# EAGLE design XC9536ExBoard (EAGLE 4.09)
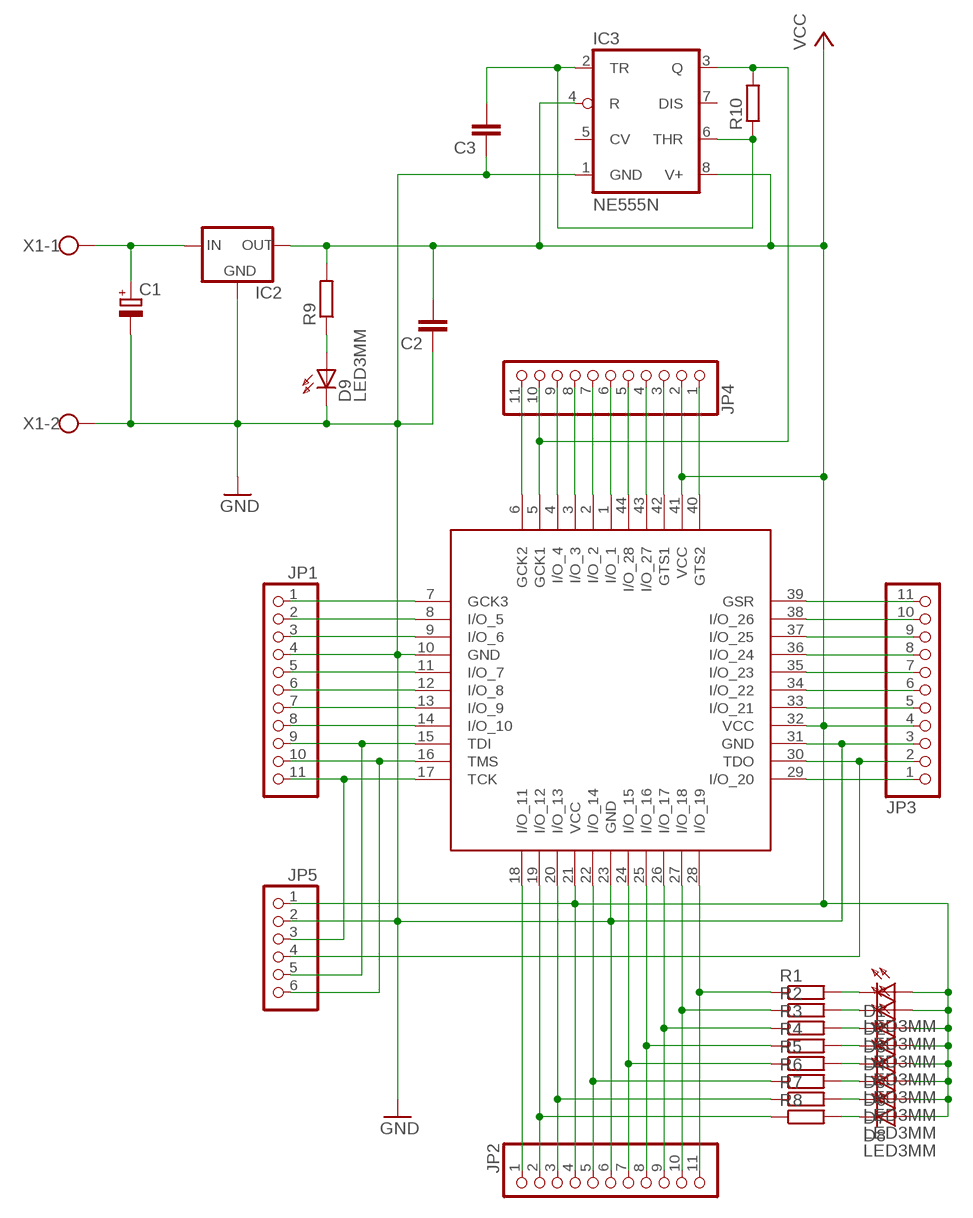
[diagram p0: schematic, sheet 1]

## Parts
C1  CPOL-EUE2.5-6  [E2,5-6]
C2  C-EU050-025X075  [C050-025X075]
C3  C-EU050-025X075  [C050-025X075]
D1  LED3MM  [LED3MM]
D2  LED3MM  [LED3MM]
D3  LED3MM  [LED3MM]
D4  LED3MM  [LED3MM]
D5  LED3MM  [LED3MM]
D6  LED3MM  [LED3MM]
D7  LED3MM  [LED3MM]
D8  LED3MM  [LED3MM]
D9  LED3MM  [LED3MM]
IC1  XC9536PLCC44S  [S44]
IC2  78XXL  [78XXL]
IC3  NE555N  [DIL08]
JP1  PINHD-1X11  [1X11]
JP2  PINHD-1X11  [1X11]
JP3  PINHD-1X11  [1X11]
JP4  PINHD-1X11  [1X11]
JP5  PINHD-1X6  [1X06]
R1  R-EU_0207/10  [0207/10]
R2  R-EU_0207/10  [0207/10]
R3  R-EU_0207/10  [0207/10]
R4  R-EU_0207/10  [0207/10]
R5  R-EU_0207/10  [0207/10]
R6  R-EU_0207/10  [0207/10]
R7  R-EU_0207/10  [0207/10]
R8  R-EU_0207/10  [0207/10]
R9  R-EU_0207/10  [0207/10]
R10  R-EU_0207/10  [0207/10]
X1  W237-02P  [W237-132]

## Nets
GND: C1.- C2.1 C3.1 D9.K(C) IC1.10(GND) IC1.23(GND) IC1.31(GND) IC2.GND IC3.1(GND) JP1.4 JP2.6 JP3.3 JP5.2 X1.2
N$1: IC1.18(I/O_11) JP2.1
N$2: IC1.19(I/O_12) JP2.2 R8.1
N$3: IC1.7(GCK3) JP1.1
N$4: IC1.8(I/O_5) JP1.2
N$5: IC1.9(I/O_6) JP1.3
N$6: IC1.11(I/O_7) JP1.5
N$7: IC1.12(I/O_8) JP1.6
N$8: IC1.13(I/O_9) JP1.7
N$9: IC1.14(I/O_10) JP1.8
N$10: IC1.15(TDI) JP1.9 JP5.5
N$11: IC1.16(TMS) JP1.10 JP5.6
N$12: IC1.17(TCK) JP1.11 JP5.3
N$13: IC1.20(I/O_13) JP2.3 R7.1
N$14: D1.K(C) R1.2
N$15: IC1.22(I/O_14) JP2.5 R6.1
N$16: IC1.24(I/O_15) JP2.7 R5.1
N$17: IC1.25(I/O_16) JP2.8 R4.1
N$18: IC1.26(I/O_17) JP2.9 R3.1
N$19: IC1.27(I/O_18) JP2.10 R2.1
N$20: IC1.28(I/O_19) JP2.11 R1.1
N$21: IC1.29(I/O_20) JP3.1
N$22: IC1.30(TDO) JP3.2 JP5.4
N$23: D2.K(C) R2.2
N$24: IC1.33(I/O_21) JP3.5
N$25: IC1.34(I/O_22) JP3.6
N$26: IC1.35(I/O_23) JP3.7
N$27: IC1.36(I/O_24) JP3.8
N$28: IC1.37(I/O_25) JP3.9
N$29: IC1.38(I/O_26) JP3.10
N$30: IC1.39(GSR) JP3.11
N$31: IC1.40(GTS2) JP4.1
N$32: D3.K(C) R3.2
N$33: IC1.42(GTS1) JP4.3
N$34: IC1.43(I/O_27) JP4.4
N$35: IC1.44(I/O_28) JP4.5
N$36: IC1.1(I/O_1) JP4.6
N$37: IC1.2(I/O_2) JP4.7
N$38: IC1.3(I/O_3) JP4.8
N$39: IC1.4(I/O_4) JP4.9
N$40: IC1.5(GCK1) IC3.3(Q) JP4.10 R10.2
N$41: IC1.6(GCK2) JP4.11
N$42: D4.K(C) R4.2
N$43: D5.K(C) R5.2
N$44: D6.K(C) R6.2
N$45: D7.K(C) R7.2
N$46: D8.K(C) R8.2
N$47: C1.+ IC2.IN X1.1
N$48: D9.A R9.1
N$50: C3.2 IC3.2(TR) IC3.6(THR) R10.1
VCC: C2.2 D1.A D2.A D3.A D4.A D5.A D6.A D7.A D8.A IC1.21(VCC) IC1.32(VCC) IC1.41(VCC) IC2.OUT IC3.4(R) IC3.8(V+) JP2.4 JP3.4 JP4.2 JP5.1 R9.2
Unconnected: IC3.5(CV) IC3.7(DIS)

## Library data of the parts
C1 = rcl:CPOL-EU: POLARIZED CAPACITOR, European symbol
C2 C3 = rcl:C-EU: CAPACITOR, European symbol
D1-D9 = led:LED3MM: LED
IC1 = xilinx:XC9536: Xilinx CPLD Cells 36 Gates 800
IC2 = v-reg:78XXL: VOLTAGE REGULATOR
IC3 = linear:*555: TIMER
JP1-JP4 = pinhead:PINHD-1X11: PIN HEADER
JP5 = pinhead:PINHD-1X6: PIN HEADER
R1-R10 = rcl:R-EU_: RESISTOR, European symbol
X1 = con-wago-508:W237-02P: WAGO SREW CLAMP

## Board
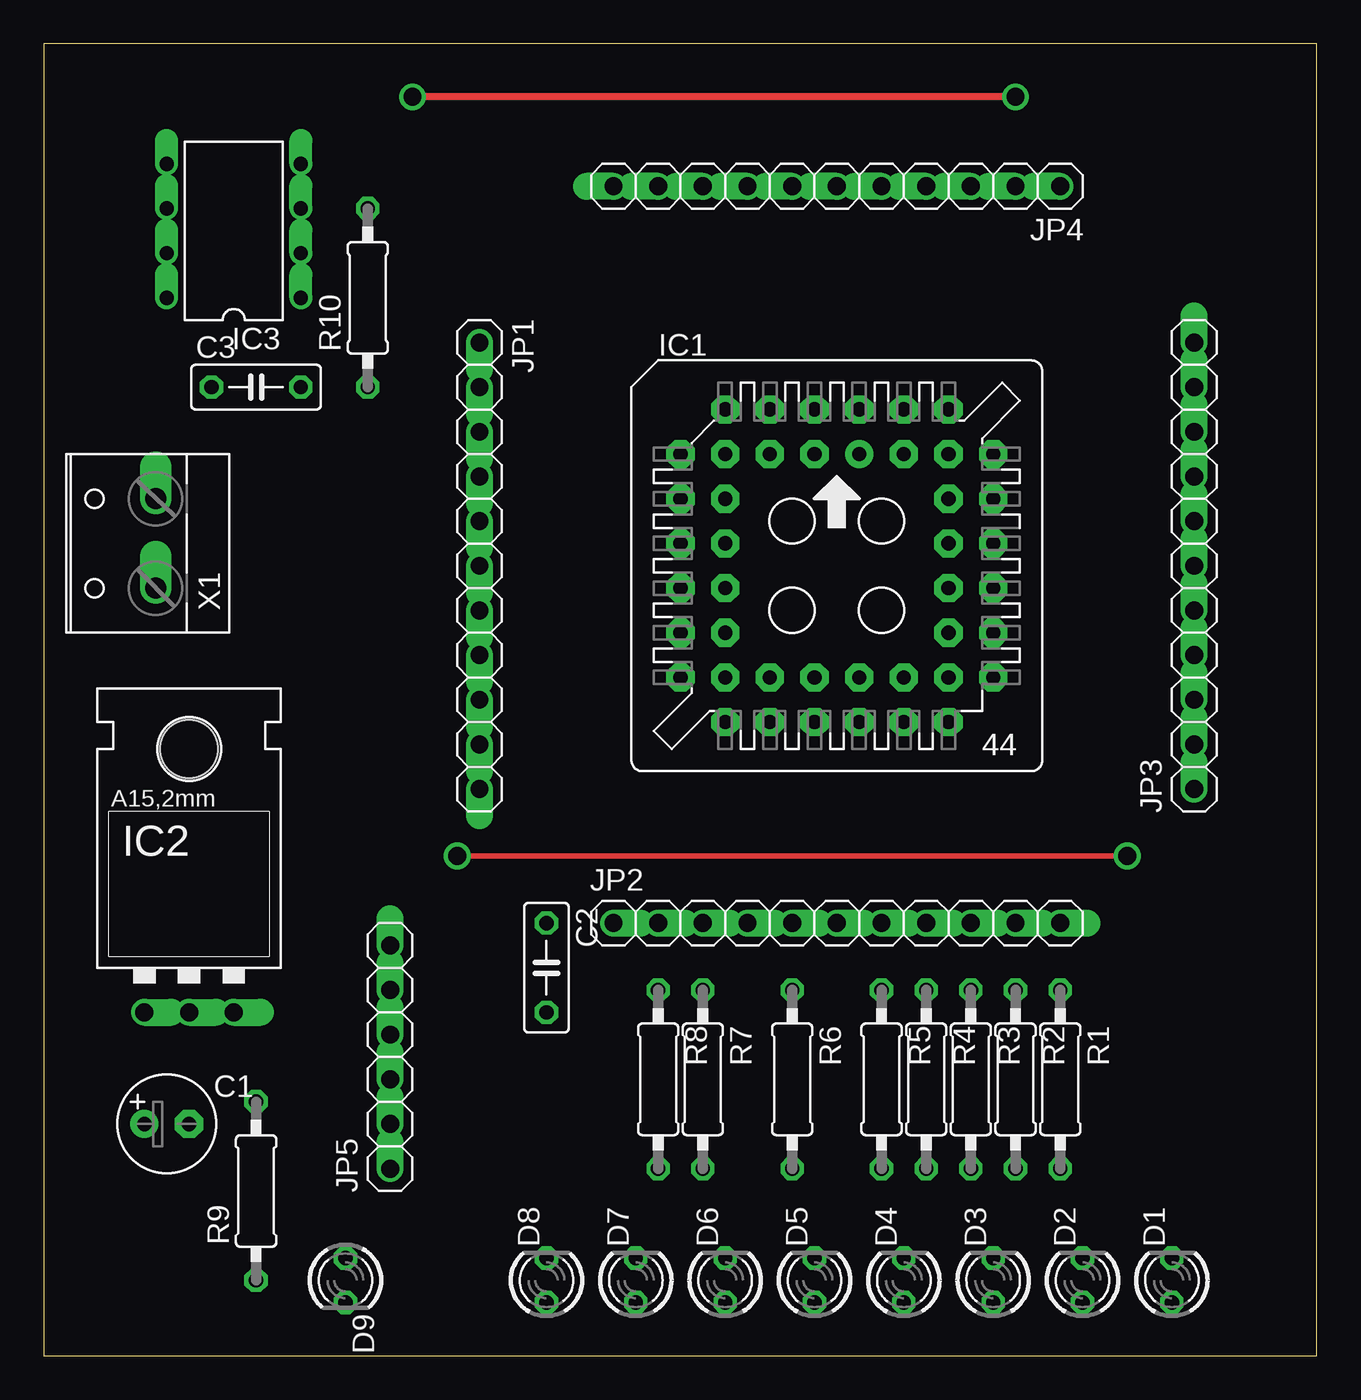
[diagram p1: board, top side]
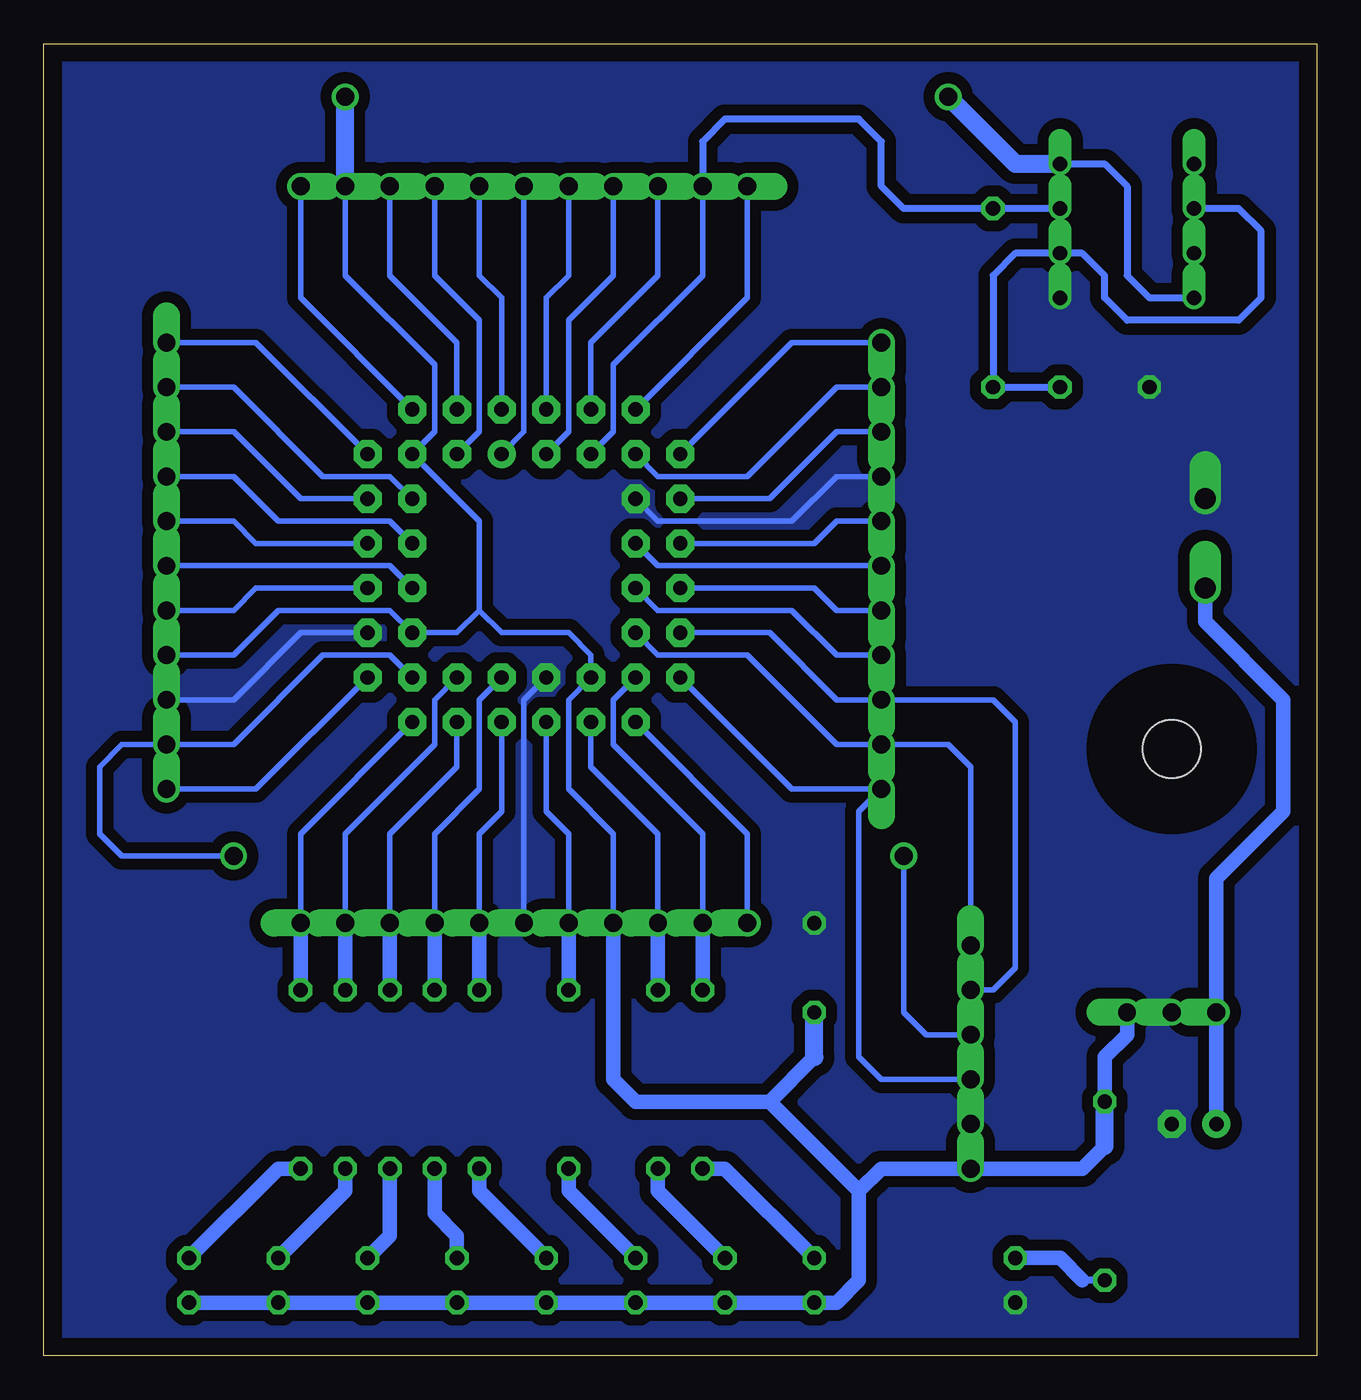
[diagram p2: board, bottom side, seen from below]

Size 72.37 x 74.6 mm. Coordinates in mm from the lower left corner, seen from the top.
Outline: 0,0 72.37,0 72.37,74.6 0,74.6 0,0
Copper layers used: Top, Bottom

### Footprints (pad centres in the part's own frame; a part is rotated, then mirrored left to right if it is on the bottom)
E2,5-6 = drill 0.813 pad 1.6 round: + -1.27,0 | drill 0.813 pad 1.6 octagon: - 1.27,0
C050-025X075 = drill 0.813 octagon: 1 -2.54,0; 2 2.54,0
LED3MM = drill 0.813 octagon: A -1.27,0; K 1.27,0
S44 = drill 0.813 pad 1.6 round: 1 1.27,5.08 | drill 0.813 pad 1.6 octagon: 2 -1.27,7.62; 3 -1.27,5.08; 4 -3.81,7.62; 5 -3.81,5.08; 6 -6.35,7.62; 7 -8.89,5.08; 8 -6.35,5.08; 9 -8.89,2.54; 10 -6.35,2.54; 11 -8.89,0; 12 -6.35,0; 13 -8.89,-2.54; 14 -6.35,-2.54; 15 -8.89,-5.08; 16 -6.35,-5.08; 17 -8.89,-7.62; 18 -6.35,-10.16; 19 -6.35,-7.62; 20 -3.81,-10.16; 21 -3.81,-7.62; 22 -1.27,-10.16; 23 -1.27,-7.62; 24 1.27,-10.16; 25 1.27,-7.62; 26 3.81,-10.16; 27 3.81,-7.62; 28 6.35,-10.16; 29 8.89,-7.62; 30 6.35,-7.62; 31 8.89,-5.08; 32 6.35,-5.08; 33 8.89,-2.54; 34 6.35,-2.54; 35 8.89,0; 36 6.35,0; 37 8.89,2.54; 38 6.35,2.54; 39 8.89,5.08; 40 6.35,7.62; 41 6.35,5.08; 42 3.81,7.62; 43 3.81,5.08; 44 1.27,7.62
78XXL = drill 1.016 offset: GND 0,-3.81; IN -2.54,-3.81; OUT 2.54,-3.81 | hole 3.302: 0,11.176
DIL08 = drill 0.813 offset: 1 -3.81,-3.81; 2 -1.27,-3.81; 3 1.27,-3.81; 4 3.81,-3.81; 5 3.81,3.81; 6 1.27,3.81; 7 -1.27,3.81; 8 -3.81,3.81
1X11 = drill 1.016 offset: 1 -12.7,0; 2 -10.16,0; 3 -7.62,0; 4 -5.08,0; 5 -2.54,0; 6 0,0; 7 2.54,0; 8 5.08,0; 9 7.62,0; 10 10.16,0; 11 12.7,0
1X06 = drill 1.016 offset: 1 -6.35,0; 2 -3.81,0; 3 -1.27,0; 4 1.27,0; 5 3.81,0; 6 6.35,0
0207/10 = drill 0.813 octagon: 1 -5.08,0; 2 5.08,0
W237-132 = drill 1.194 offset: 1 -2.54,-0.635; 2 2.54,-0.635

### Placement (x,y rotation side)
C1  6.98,13.17 0 top
C2  28.57,22.06 270 top
C3  12.06,55.08 0 top
D1  64.13,4.28 90 top
D2  59.05,4.28 90 top
D3  53.97,4.28 90 top
D4  48.89,4.28 90 top
D5  43.81,4.28 90 top
D6  38.73,4.28 90 top
D7  33.65,4.28 90 top
D8  28.57,4.28 90 top
D9  17.14,4.28 270 top
IC1  45.08,46.19 0 top
IC2  8.25,23.33 0 top
IC3  10.79,63.97 90 top
JP1  24.76,44.92 270 top
JP2  45.08,24.6 0 top
JP3  65.4,44.92 90 top
JP4  45.08,66.51 180 top
JP5  19.68,16.98 90 top
R1  57.78,15.71 270 top
R2  55.24,15.71 270 top
R3  52.7,15.71 270 top
R4  50.16,15.71 270 top
R5  47.62,15.71 270 top
R6  42.54,15.71 270 top
R7  37.46,15.71 270 top
R8  34.92,15.71 270 top
R9  12.06,9.36 90 top
R10  18.41,60.16 90 top
X1  5.71,46.19 90 top

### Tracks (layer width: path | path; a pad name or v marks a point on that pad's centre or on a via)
GND
  Bottom 0.305: JP1.4 27.3,50 29.84,47.46 37.46,47.46 IC1.10 | IC1.31 57.78,41.11 61.59,37.3 JP3.3 | IC1.23 45.08,37.3 JP2.6
  pour Bottom (isolate 0.635, no thermals): 0.63,74.13 0.63,0.47 71.75,0.47 71.75,74.13
N$1
  Bottom 0.305: JP2.1 32.38,29.68 IC1.18
N$2
  Bottom 0.305: IC1.19 40,37.3 40,34.76 34.92,29.68 JP2.2
  Bottom 0.813: R8.1 JP2.2
N$3
  Bottom 0.305: JP1.1 29.84,57.62 IC1.7
N$4
  Bottom 0.305: IC1.8 37.46,50 32.38,50 27.3,55.08 JP1.2
N$5
  Bottom 0.305: IC1.9 31.11,48.73 27.3,52.54 JP1.3
N$6
  Bottom 0.305: IC1.11 28.57,46.19 27.3,47.46 JP1.5
N$7
  Bottom 0.305: JP1.6 37.46,44.92 IC1.12
N$8
  Bottom 0.305: IC1.13 28.57,43.65 27.3,42.38 JP1.7
N$9
  Bottom 0.305: JP1.8 27.3,39.84 29.84,42.38 37.46,42.38 IC1.14
N$10
  Bottom 0.305: IC1.15 31.11,41.11 27.3,37.3 JP1.9 18.41,37.3 17.14,36.03 17.14,22.06 18.41,20.79 JP5.5
N$11
  Bottom 0.305: IC1.16 37.46,39.84 32.38,39.84 27.3,34.76 JP1.10 20.95,34.76 19.68,33.49 JP5.6
N$12
  Bottom 0.305: IC1.17 29.84,32.22 JP1.11 26.03,30.95 26.03,16.98 24.76,15.71 JP5.3
N$13
  Bottom 0.305: JP2.3 37.46,29.68 41.27,33.49 IC1.20
  Bottom 0.813: R7.1 JP2.3
N$14
  Bottom 0.813: D1.K 59.05,10.63 R1.2
N$15
  Bottom 0.305: JP2.5 42.54,29.68 43.81,30.95 IC1.22
  Bottom 0.813: R6.1 JP2.5
N$16
  Bottom 0.305: IC1.24 46.35,30.95 47.62,29.68 JP2.7
  Bottom 0.813: R5.1 JP2.7
N$17
  Bottom 0.305: IC1.25 47.62,37.3 47.62,32.22 50.16,29.68 JP2.8
  Bottom 0.813: R4.1 JP2.8
N$18
  Bottom 0.305: IC1.26 48.89,33.49 52.7,29.68 JP2.9
  Bottom 0.813: R3.1 JP2.9
N$19
  Bottom 0.305: IC1.27 50.16,37.3 50.16,34.76 55.24,29.68 JP2.10
  Bottom 0.813: R2.1 JP2.10
N$20
  Bottom 0.305: IC1.28 57.78,29.68 JP2.11
  Bottom 0.813: R1.1 JP2.11
N$21
  Bottom 0.305: IC1.29 60.32,32.22 JP3.1
N$22  (via drill 1.02)
  Top 0.305: v23.49,28.41 v61.59,28.41
  Bottom 0.305: IC1.30 52.7,39.84 56.51,39.84 61.59,34.76 JP3.2 67.94,34.76 69.21,33.49 69.21,29.68 67.94,28.41 v61.59,28.41 | JP5.4 22.22,18.25 23.49,19.52 v23.49,28.41
N$23
  Bottom 0.813: D2.K 55.24,9.36 R2.2
N$24
  Bottom 0.305: IC1.33 60.32,43.65 61.59,42.38 JP3.5
N$25
  Bottom 0.305: IC1.34 52.7,44.92 JP3.6
N$26
  Bottom 0.305: IC1.35 60.32,46.19 61.59,47.46 JP3.7
N$27
  Bottom 0.305: IC1.36 52.7,47.46 59.05,47.46 61.59,50 JP3.8
N$28
  Bottom 0.305: IC1.37 57.78,48.73 61.59,52.54 JP3.9
N$29
  Bottom 0.305: IC1.38 52.7,50 56.51,50 61.59,55.08 JP3.10
N$30
  Bottom 0.305: IC1.39 60.32,57.62 JP3.11
N$31
  Bottom 0.305: IC1.40 57.78,60.16 JP4.1
N$32
  Bottom 0.813: D3.K 52.7,6.82 R3.2
N$33
  Bottom 0.305: IC1.42 48.89,57.62 52.7,61.43 JP4.3
N$34
  Bottom 0.305: IC1.43 47.62,52.54 47.62,58.89 50.16,61.43 JP4.4
N$35
  Bottom 0.305: IC1.44 46.35,60.16 47.62,61.43 JP4.5
N$36
  Bottom 0.305: IC1.1 45.08,52.54 JP4.6
N$37
  Bottom 0.305: IC1.2 43.81,60.16 42.54,61.43 JP4.7
N$38
  Bottom 0.305: JP4.8 40,61.43 42.54,58.89 42.54,52.54 IC1.3
N$39
  Bottom 0.305: IC1.4 41.27,57.62 37.46,61.43 JP4.9
N$40
  Bottom 0.305: IC1.5 40,52.54 40,56.35 34.92,61.43 JP4.10
  Bottom 0.406: IC3.3 R10.2 23.49,65.24 24.76,66.51 24.76,69.05 26.03,70.32 33.65,70.32 34.92,69.05 JP4.10
N$41
  Bottom 0.305: JP4.11 32.38,60.16 IC1.6
N$42
  Bottom 0.813: D4.K 48.89,6.82 50.16,8.09 R4.2
N$43
  Bottom 0.813: D5.K 47.62,9.36 R5.2
N$44
  Bottom 0.813: D6.K 42.54,9.36 R6.2
N$45
  Bottom 0.813: D7.K 37.46,9.36 R7.2
N$46
  Bottom 0.813: R8.2 33.65,10.63 D8.K
N$47
  Bottom 0.813: C1.+ IC2.IN 5.71,27.14 1.9,30.95 1.9,37.3 6.34,41.74 X1.1
N$48
  Bottom 0.406: R9.1 13.33,4.28
  Bottom 0.813: 13.33,4.28 14.6,5.55 D9.A
N$50
  Bottom 0.406: C3.2 R10.1 18.41,61.43 17.14,62.7 IC3.2 13.33,62.7 12.06,61.43 12.06,60.16 10.79,58.89 4.44,58.89 3.17,60.16 3.17,63.97 4.44,65.24 IC3.6
VCC  (via drill 1.02)
  Top 0.406: v55.24,71.59 v20.95,71.59
  Bottom 0.305: JP3.4 61.59,39.84 59.05,42.38 52.7,42.38 IC1.32 48.89,41.11 47.62,42.38 | JP2.4 40,29.68 42.54,32.22 42.54,37.3 IC1.21 41.27,39.84 42.54,41.11 46.35,41.11 47.62,42.38 | JP4.2 55.24,61.43 50.16,56.35 50.16,52.54 IC1.41 47.62,47.46 47.62,42.38
  Bottom 0.406: IC3.8 9.52,60.16 10.79,61.43 10.79,66.51 12.06,67.78 IC3.4
  Bottom 0.813: 31.11,14.44 38.73,14.44 40,15.71 JP2.4 | D1.A D2.A D3.A D4.A D5.A D6.A D7.A D8.A 27.3,3.01 26.03,4.28 26.03,9.36 | 26.03,9.36 24.76,10.63 JP5.1 13.33,10.63 12.06,11.9 | 26.03,9.36 31.11,14.44 | 31.11,14.44 28.57,16.98 | IC2.OUT 10.79,18.25 12.06,16.98 R9.2
  Bottom 1.016: IC3.4 17.14,67.78 v20.95,71.59 | JP4.2 v55.24,71.59 | 12.06,11.9 R9.2 | 28.57,16.98 C2.2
